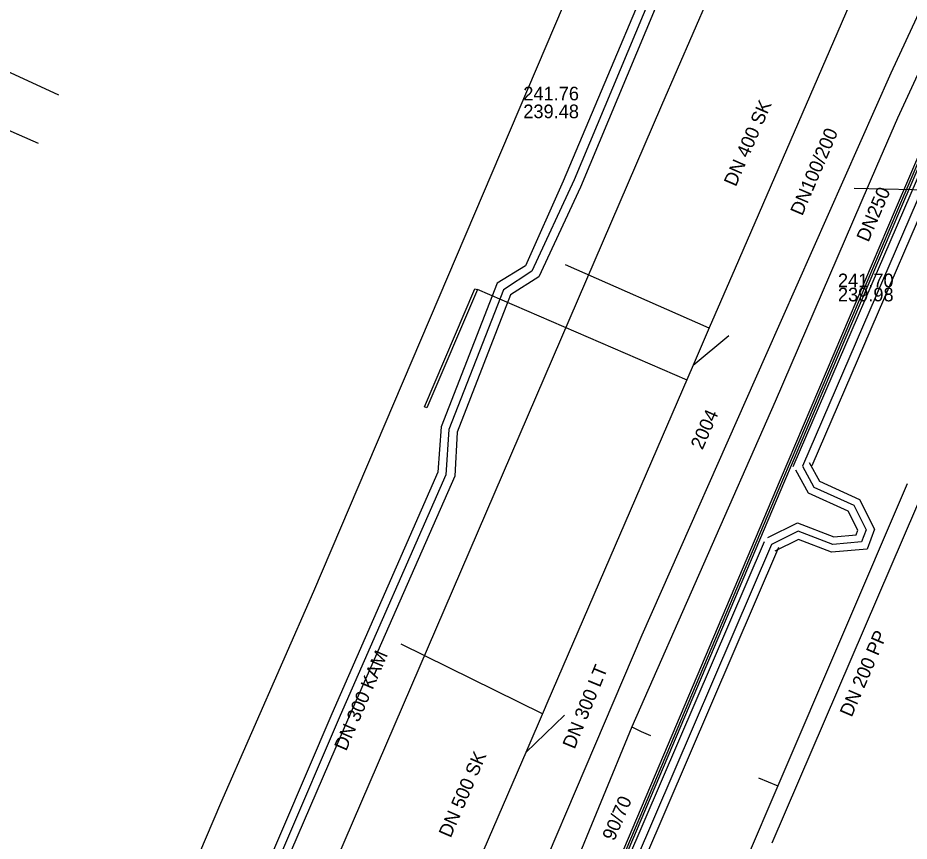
# Model space of a CAD drawing. Extents: x -596024 to -594475, y -1163820 to -1161957.
# Drawn here: x -594746.6 to -594694.2, y -1162321.3 to -1162272.9 of the extents above; entities that cross this region are included whole.
import ezdxf

# ---------------------------------------------------------------- set-up
doc = ezdxf.new("R2010")
doc.units = 0
for name, color, linetype in [('Level 1', 7, 'Continuous'), ('Level 3', 7, 'Continuous'), ('Vrstva 1', 7, 'Continuous'), ('Vrstva 12', 7, 'Continuous'), ('Vrstva 13', 7, 'Continuous'), ('Vrstva 15', 7, 'Continuous'), ('Vrstva 19', 7, 'Continuous'), ('Vrstva 29', 7, 'Continuous'), ('Vrstva 30', 7, 'Continuous'), ('Vrstva 32', 7, 'Continuous'), ('Vrstva 4', 7, 'Continuous'), ('Vrstva 5', 7, 'Continuous'), ('Vrstva 55', 7, 'Continuous'), ('Vrstva 8', 7, 'Continuous'), ('Vrstva 9', 7, 'Continuous')]:
    doc.layers.add(name, color=color, linetype=linetype)

msp = doc.modelspace()

# ---------------------------------------------------------------- linework, layer by layer
at = {"layer": 'Level 1'}
for points in [[(-594705.94, -1162291.17), (-594714.38, -1162287.45)], [(-594707.24, -1162294.24), (-594719.56, -1162288.91)], [(-594706.88, -1162293.35), (-594704.79, -1162291.6)], [(-594715.74, -1162313.86), (-594724.04, -1162309.75)], [(-594716.71, -1162316.12), (-594714.44, -1162313.93)]]:
    msp.add_lwpolyline(points, dxfattribs=at)
at = {"layer": 'Level 3'}
msp.add_lwpolyline([(-594719.7, -1162288.86), (-594719.56, -1162288.91), (-594722.53, -1162295.87), (-594722.67, -1162295.81)], close=True, dxfattribs=at)
at = {"layer": 'Vrstva 1'}
for p, q in [((-594744.151, -1162277.481), (-594758.849, -1162270.671)), ((-594703.046, -1162317.612), (-594701.902, -1162318.094))]:
    msp.add_line(p, q, dxfattribs=at)
for points in [[(-594688.44, -1162250.8), (-594689.269, -1162252.711), (-594689.388, -1162252.986), (-594696.244, -1162268.804), (-594696.296, -1162268.923), (-594696.745, -1162269.96), (-594696.769, -1162270.015), (-594704.41, -1162287.64)], [(-594704.41, -1162287.64), (-594705.931, -1162291.161), (-594706.879, -1162293.355), (-594715.47, -1162313.239), (-594715.633, -1162313.615), (-594716.66, -1162315.993), (-594721.51, -1162327.22)], [(-594694.31, -1162300.33), (-594701.902, -1162318.094), (-594703.76, -1162322.44)]]:
    msp.add_lwpolyline(points, dxfattribs=at)
at = {"layer": 'Vrstva 12'}
msp.add_lwpolyline([(-594705.05, -1162250), (-594729.19, -1162306.66), (-594734.66, -1162319.12), (-594741.38, -1162334.97), (-594741.86, -1162336.56)], dxfattribs=at)
at = {"layer": 'Vrstva 13'}
for points in [[(-594651.55, -1162212.94), (-594652.09, -1162214.3), (-594654.4, -1162217.32), (-594658.53, -1162224.58), (-594666.86, -1162243.95), (-594667.56, -1162244.58), (-594677.47, -1162243.87), (-594678.66, -1162244.27), (-594679.14, -1162245.09), (-594685.17, -1162257.8), (-594694.88, -1162278.83), (-594696.109, -1162281.678), (-594702.06, -1162295.48), (-594710.48, -1162314.62), (-594714.12, -1162323.47), (-594715.655, -1162327.014), (-594723.77, -1162345.59), (-594733.52, -1162367.83)], [(-594710.48, -1162314.62), (-594709.94, -1162314.9), (-594709.39, -1162315.12)]]:
    msp.add_lwpolyline(points, dxfattribs=at)
at = {"layer": 'Vrstva 19'}
msp.add_lwpolyline([(-594746.52, -1162394.18), (-594746.25, -1162393.56), (-594744.21, -1162388.64), (-594738.04, -1162374.42), (-594735.09, -1162367.58), (-594734.777, -1162366.85), (-594727.36, -1162349.54), (-594719.29, -1162331.31), (-594709.88, -1162309.21), (-594702.61, -1162292.78), (-594695.25, -1162276.17), (-594690.21, -1162265.28)], dxfattribs=at)
at = {"layer": 'Vrstva 29'}
for p, q in [((-594681.506, -1162255.298), (-594700.461, -1162299.3)), ((-594702.281, -1162303.892), (-594725.841, -1162358.76))]:
    msp.add_line(p, q, dxfattribs=at)
for points in [[(-594682.163, -1162255.044), (-594688.255, -1162268.82), (-594694.869, -1162284.243), (-594701.636, -1162300.121), (-594708.486, -1162316.32), (-594713.19, -1162327.409), (-594724.729, -1162354.081), (-594733.369, -1162373.523), (-594739.658, -1162387.067), (-594743.699, -1162395.9), (-594745.794, -1162400.435)], [(-594700.461, -1162299.3), (-594699.782, -1162300.526), (-594697.442, -1162301.586), (-594696.714, -1162303.027), (-594696.983, -1162303.743), (-594698.68, -1162303.898), (-594700.717, -1162303.107), (-594702.281, -1162303.892)]]:
    msp.add_lwpolyline(points, dxfattribs=at)
at = {"layer": 'Vrstva 30'}
for p, q in [((-594680.743, -1162254.789), (-594699.905, -1162299.273)), ((-594682.27, -1162255.808), (-594701.017, -1162299.327)), ((-594726.254, -1162358.582), (-594702.694, -1162303.714)), ((-594701.868, -1162304.07), (-594725.428, -1162358.938))]:
    msp.add_line(p, q, dxfattribs=at)
for points in [[(-594745.914, -1162400.396), (-594743.813, -1162395.848), (-594739.772, -1162387.015), (-594733.483, -1162373.471), (-594724.843, -1162354.031), (-594713.305, -1162327.36), (-594708.601, -1162316.271), (-594701.751, -1162300.072), (-594694.984, -1162284.194), (-594688.37, -1162268.77), (-594682.277, -1162254.993)], [(-594682.049, -1162255.095), (-594688.14, -1162268.87), (-594694.754, -1162284.292), (-594701.521, -1162300.17), (-594708.371, -1162316.369), (-594713.075, -1162327.458), (-594724.615, -1162354.131), (-594733.255, -1162373.575), (-594739.544, -1162387.119), (-594743.585, -1162395.952), (-594745.674, -1162400.473)], [(-594700.067, -1162299.082), (-594699.461, -1162300.178), (-594697.112, -1162301.242), (-594696.223, -1162303), (-594696.661, -1162304.165), (-594698.744, -1162304.356), (-594700.694, -1162303.599), (-594702.079, -1162304.294)], [(-594702.483, -1162303.49), (-594700.74, -1162302.615), (-594698.616, -1162303.44), (-594697.305, -1162303.321), (-594697.205, -1162303.054), (-594697.772, -1162301.93), (-594700.103, -1162300.874), (-594700.855, -1162299.518)]]:
    msp.add_lwpolyline(points, dxfattribs=at)
at = {"layer": 'Vrstva 5'}
for p, q in [((-594693.47, -1162242.94), (-594708.74, -1162278.08)), ((-594708.74, -1162278.08), (-594728.45, -1162323.84)), ((-594691.52, -1162296.45), (-594702.26, -1162321.46))]:
    msp.add_line(p, q, dxfattribs=at)
msp.add_lwpolyline([(-594627.118, -1162316.188), (-594625.912, -1162313.061), (-594625.908, -1162311.536), (-594634.05, -1162308.137), (-594651.143, -1162300.77), (-594689.133, -1162284.403), (-594692.186, -1162283.089), (-594697.41, -1162282.969)], dxfattribs=at)
at = {"layer": 'Vrstva 55'}
for points in [[(-594704.41, -1162254.33), (-594704.3, -1162255.33), (-594702.93, -1162255.73), (-594704.35, -1162258.82), (-594707.28, -1162265.39), (-594714.51, -1162282.54), (-594716.73, -1162287.52), (-594718.4, -1162288.53), (-594721.68, -1162296.97), (-594721.88, -1162299.65), (-594728.1, -1162313.86), (-594741.09, -1162344.23), (-594742.55, -1162346.15), (-594748.77, -1162359.67), (-594748.92, -1162361.59), (-594758.77, -1162384.82), (-594763.82, -1162396.17), (-594769.74, -1162409.74), (-594769.89, -1162410.8), (-594782.62, -1162440.24), (-594796.22, -1162471.4), (-594809.91, -1162502.76)], [(-594704.41, -1162254.33), (-594703.94, -1162254.92), (-594702.27, -1162255.37), (-594706.67, -1162265.19), (-594713.87, -1162282.45), (-594716.36, -1162287.83), (-594718.03, -1162288.92), (-594721.24, -1162297.13), (-594721.41, -1162299.81), (-594727.62, -1162313.95), (-594740.7, -1162344.52), (-594742.24, -1162346.53), (-594748.26, -1162359.89), (-594748.43, -1162361.79), (-594758.27, -1162384.99), (-594763.4, -1162396.37), (-594769.2, -1162409.93), (-594769.43, -1162410.91), (-594776.51, -1162427.37), (-594782.06, -1162440.27), (-594795.59, -1162471.33), (-594809.31, -1162502.78)], [(-594704.41, -1162254.33), (-594701.47, -1162254.94), (-594703.5, -1162259.27), (-594706.37, -1162265.79), (-594713.5, -1162282.88), (-594715.94, -1162288.16), (-594717.61, -1162289.22), (-594720.75, -1162297.3), (-594720.89, -1162299.87), (-594727.14, -1162314.09), (-594739.222, -1162342.089), (-594740.23, -1162344.7), (-594741.867, -1162348.428), (-594743.706, -1162347.671)]]:
    msp.add_lwpolyline(points, dxfattribs=at)
at = {"layer": 'Vrstva 9'}
msp.add_line((-594745.351, -1162280.322), (-594759.387, -1162274.105), dxfattribs=at)

# ---------------------------------------------------------------- texts
at = {"layer": 'Vrstva 15'}
for s, rotation, p in [('2004', 66.2339, (-594706.332, -1162298.369)), ('DN 300 LT', 67.6663, (-594713.849, -1162315.972))]:
    msp.add_text(s, height=0.8, rotation=rotation, dxfattribs=at).set_placement(p)
at = {"layer": 'Vrstva 32'}
for s, rotation, p in [('DN100/200', 66.9215, (-594700.47, -1162284.612)), ('DN250', 66.6948, (-594696.585, -1162286.162)), ('90/70', 66.7616, (-594711.518, -1162321.37))]:
    msp.add_text(s, height=0.8, rotation=rotation, dxfattribs=at).set_placement(p)
at = {"layer": 'Vrstva 4'}
for s, rotation, p in [('DN 400 SK', 66.5777, (-594704.375, -1162282.899)), ('DN 500 SK', 66.635, (-594721.13, -1162321.19))]:
    msp.add_text(s, height=0.8, rotation=rotation, dxfattribs=at).set_placement(p)
for s, p in [('241.70', (-594698.373, -1162288.768)), ('239.98', (-594698.373, -1162289.6))]:
    msp.add_text(s, height=0.8, dxfattribs=at).set_placement(p)
at = {"layer": 'Vrstva 8'}
for s, p in [('241.76', (-594716.86, -1162277.78)), ('239.48', (-594716.86, -1162278.83))]:
    msp.add_text(s, height=0.8, dxfattribs=at).set_placement(p)
for s, rotation, p in [('DN 200 PP', 66.76, (-594697.566, -1162314.092)), ('DN 300 KAM', 66.6923, (-594727.268, -1162316.085))]:
    msp.add_text(s, height=0.8, rotation=rotation, dxfattribs=at).set_placement(p)

doc.saveas('drawing.dxf')
